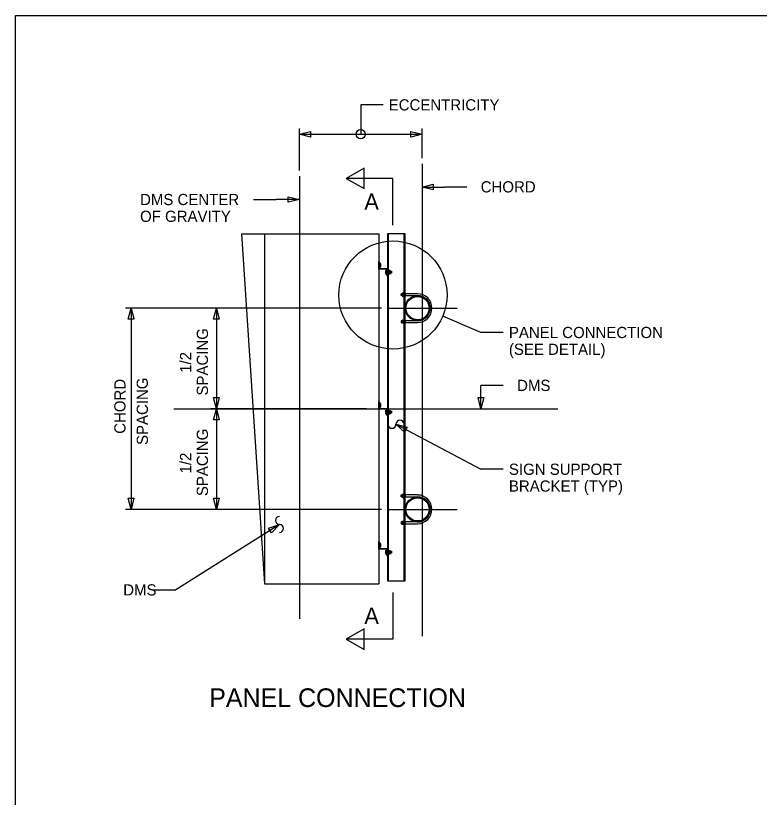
# Model space of a CAD drawing. Extents: x 3831399 to 3833095, y 499014 to 500202.
# Drawn here: x 3832280.2 to 3832479.3, y 499383.6 to 499593 of the extents above; entities that cross this region are included whole.
import ezdxf

# ---------------------------------------------------------------- set-up
doc = ezdxf.new("R2010")
doc.units = 0
for name, color, linetype in [('0-ANCHOR', 7, 'Continuous'), ('2', 7, 'Continuous'), ('CNTR', 7, 'Continuous'), ('Default', 7, 'Continuous'), ('DIM TXT', 7, 'Continuous'), ('sign', 7, 'Continuous'), ('structure', 7, 'Continuous')]:
    doc.layers.add(name, color=color, linetype=linetype)

msp = doc.modelspace()

# ---------------------------------------------------------------- linework, layer by layer
at = {"layer": '0-ANCHOR'}
for p, q in [((3832377.88, 499526.58), (3832377.58, 499526.58)), ((3832377.58, 499526.58), (3832377.58, 499525.75)), ((3832377.88, 499526.37), (3832377.58, 499526.37)), ((3832377.88, 499525.95), (3832377.58, 499525.95)), ((3832377.58, 499525.75), (3832377.88, 499525.75)), ((3832377.92, 499525.79), (3832377.92, 499526.53)), ((3832379.19, 499524.67), (3832379.19, 499523.94)), ((3832379.53, 499524.72), (3832379.24, 499524.72)), ((3832379.53, 499523.89), (3832379.53, 499524.72)), ((3832380.04, 499524.55), (3832379.53, 499524.55)), ((3832380.43, 499524.72), (3832380.04, 499524.72)), ((3832380.04, 499524.72), (3832380.04, 499523.89)), ((3832380.04, 499524.06), (3832380.04, 499524.55)), ((3832380.48, 499523.94), (3832380.48, 499524.67)), ((3832380.48, 499524.55), (3832380.82, 499524.55)), ((3832380.82, 499524.55), (3832380.82, 499524.06)), ((3832379.24, 499524.51), (3832379.53, 499524.51)), ((3832379.24, 499524.1), (3832379.53, 499524.1)), ((3832379.24, 499523.89), (3832379.53, 499523.89)), ((3832379.53, 499524.06), (3832380.04, 499524.06)), ((3832380.04, 499524.51), (3832380.43, 499524.51)), ((3832380.04, 499524.1), (3832380.43, 499524.1)), ((3832380.04, 499523.89), (3832380.43, 499523.89)), ((3832380.82, 499524.06), (3832380.48, 499524.06)), ((3832377.88, 499489.08), (3832377.58, 499489.08)), ((3832377.58, 499489.08), (3832377.58, 499488.25)), ((3832377.92, 499488.29), (3832377.92, 499489.03)), ((3832377.88, 499488.87), (3832377.58, 499488.87)), ((3832377.88, 499488.46), (3832377.58, 499488.46)), ((3832377.58, 499488.25), (3832377.88, 499488.25)), ((3832379.19, 499487.18), (3832379.19, 499486.44)), ((3832379.53, 499487.22), (3832379.24, 499487.22)), ((3832379.24, 499487.02), (3832379.53, 499487.02)), ((3832379.53, 499486.39), (3832379.53, 499487.22)), ((3832380.04, 499487.05), (3832379.53, 499487.05)), ((3832380.43, 499487.22), (3832380.04, 499487.22)), ((3832380.04, 499487.22), (3832380.04, 499486.39)), ((3832380.04, 499486.56), (3832380.04, 499487.05)), ((3832380.04, 499487.02), (3832380.43, 499487.02)), ((3832380.48, 499486.44), (3832380.48, 499487.18)), ((3832380.48, 499487.05), (3832380.82, 499487.05)), ((3832380.82, 499487.05), (3832380.82, 499486.56)), ((3832379.24, 499486.6), (3832379.53, 499486.6)), ((3832379.24, 499486.39), (3832379.53, 499486.39)), ((3832379.53, 499486.56), (3832380.04, 499486.56)), ((3832380.04, 499486.6), (3832380.43, 499486.6)), ((3832380.04, 499486.39), (3832380.43, 499486.39)), ((3832380.82, 499486.56), (3832380.48, 499486.56)), ((3832377.88, 499451.58), (3832377.58, 499451.58)), ((3832377.58, 499451.58), (3832377.58, 499450.75)), ((3832377.88, 499451.37), (3832377.58, 499451.37)), ((3832377.92, 499450.8), (3832377.92, 499451.53)), ((3832377.88, 499450.96), (3832377.58, 499450.96)), ((3832377.58, 499450.75), (3832377.88, 499450.75)), ((3832379.19, 499449.68), (3832379.19, 499448.94)), ((3832379.53, 499449.72), (3832379.24, 499449.72)), ((3832379.24, 499449.52), (3832379.53, 499449.52)), ((3832379.53, 499448.89), (3832379.53, 499449.72)), ((3832380.04, 499449.55), (3832379.53, 499449.55)), ((3832380.43, 499449.72), (3832380.04, 499449.72)), ((3832380.04, 499449.72), (3832380.04, 499448.89)), ((3832380.04, 499449.06), (3832380.04, 499449.55)), ((3832380.04, 499449.52), (3832380.43, 499449.52)), ((3832380.48, 499448.94), (3832380.48, 499449.68)), ((3832380.48, 499449.55), (3832380.82, 499449.55)), ((3832380.82, 499449.55), (3832380.82, 499449.06)), ((3832379.24, 499449.1), (3832379.53, 499449.1)), ((3832379.24, 499448.89), (3832379.53, 499448.89)), ((3832379.53, 499449.06), (3832380.04, 499449.06)), ((3832380.04, 499449.1), (3832380.43, 499449.1)), ((3832380.04, 499448.89), (3832380.43, 499448.89)), ((3832380.82, 499449.06), (3832380.48, 499449.06))]:
    msp.add_line(p, q, dxfattribs=at)
for centre, start, end in [((3832377.88, 499526.53), 360, 90), ((3832377.88, 499526.42), 270, 0), ((3832377.88, 499525.91), 360, 90), ((3832377.88, 499525.79), 270, 0), ((3832379.24, 499524.67), 90, 180), ((3832379.24, 499524.56), 180, 270), ((3832380.43, 499524.67), 360, 90), ((3832380.43, 499524.56), 270, 0), ((3832379.24, 499524.05), 90, 180), ((3832379.24, 499523.94), 180, 270), ((3832380.43, 499524.05), 360, 90), ((3832380.43, 499523.94), 270, 0), ((3832377.88, 499489.03), 360, 90), ((3832377.88, 499488.92), 270, 0), ((3832377.88, 499488.41), 360, 90), ((3832377.88, 499488.29), 270, 0), ((3832379.24, 499487.18), 90, 180), ((3832379.24, 499487.06), 180, 270), ((3832380.43, 499487.18), 360, 90), ((3832380.43, 499487.06), 270, 0), ((3832379.24, 499486.55), 90, 180), ((3832379.24, 499486.44), 180, 270), ((3832380.43, 499486.55), 360, 90), ((3832380.43, 499486.44), 270, 0), ((3832377.88, 499451.53), 360, 90), ((3832377.88, 499451.42), 270, 0), ((3832377.88, 499450.91), 360, 90), ((3832377.88, 499450.8), 270, 0), ((3832379.24, 499449.68), 90, 180), ((3832379.24, 499449.56), 180, 270), ((3832380.43, 499449.68), 360, 90), ((3832380.43, 499449.56), 270, 0), ((3832379.24, 499449.05), 90, 180), ((3832379.24, 499448.94), 180, 270), ((3832380.43, 499449.05), 360, 90), ((3832380.43, 499448.94), 270, 0)]:
    msp.add_arc(centre, 0.0469, start, end, dxfattribs=at)
for centre, major_axis, start_param, end_param in [((3832377.88, 499526.24), (0, 0.129), 4.712389, 6.283185), ((3832377.88, 499526.08), (0, -0.129), 0, 1.570796), ((3832379.24, 499524.38), (0, 0.129), 0, 1.570796), ((3832379.24, 499524.23), (0, -0.129), 4.712389, 6.283185), ((3832380.43, 499524.38), (0, 0.129), 4.712389, 6.283185), ((3832380.43, 499524.23), (0, -0.129), 0, 1.570796), ((3832377.88, 499488.74), (0, 0.129), 4.712389, 6.283185), ((3832377.88, 499488.58), (0, -0.129), 0, 1.570796), ((3832379.24, 499486.89), (0, 0.129), 0, 1.570796), ((3832380.43, 499486.89), (0, 0.129), 4.712389, 6.283185), ((3832379.24, 499486.73), (0, -0.129), 4.712389, 6.283185), ((3832380.43, 499486.73), (0, -0.129), 0, 1.570796), ((3832377.88, 499451.24), (0, 0.129), 4.712389, 6.283185), ((3832377.88, 499451.09), (0, -0.129), 0, 1.570796), ((3832379.24, 499449.39), (0, 0.129), 0, 1.570796), ((3832379.24, 499449.23), (0, -0.129), 4.712389, 6.283185), ((3832380.43, 499449.39), (0, 0.129), 4.712389, 6.283185), ((3832380.43, 499449.23), (0, -0.129), 0, 1.570796)]:
    msp.add_ellipse(centre, major_axis=major_axis, ratio=0.362172, start_param=start_param, end_param=end_param, dxfattribs=at)
at = {"layer": '2'}
for p, q in [((3832280.16, 499029.03), (3832280.16, 499593.03)), ((3832280.16, 499593.03), (3833066.16, 499593.03))]:
    msp.add_line(p, q, dxfattribs=at)
at = {"layer": 'CNTR'}
for p, q in [((3832388.95, 499553.36), (3832388.95, 499426.8)), ((3832356.11, 499550.03), (3832356.11, 499431.49)), ((3832379.58, 499514.69), (3832398.32, 499514.69)), ((3832322.49, 499487.74), (3832425.31, 499487.74)), ((3832379.58, 499460.78), (3832398.32, 499460.78))]:
    msp.add_line(p, q, dxfattribs=at)
at = {"layer": 'Default'}
for p, q in [((3832373.44, 499552.2), (3832368.68, 499549.45)), ((3832373.44, 499546.7), (3832373.44, 499552.2)), ((3832368.68, 499549.45), (3832373.44, 499546.7)), ((3832373.44, 499428.77), (3832368.68, 499426.02)), ((3832373.44, 499423.27), (3832373.44, 499428.77)), ((3832368.68, 499426.02), (3832373.44, 499423.27))]:
    msp.add_line(p, q, dxfattribs=at)
at = {"layer": 'DIM TXT'}
for p, q in [((3832372.53, 499569.13), (3832372.53, 499561.26)), ((3832378.53, 499569.13), (3832372.53, 499569.13)), ((3832356.11, 499551.53), (3832356.11, 499562.76)), ((3832388.95, 499554.86), (3832388.95, 499562.76)), ((3832356.11, 499561.26), (3832388.95, 499561.26)), ((3832381.17, 499549.45), (3832368.68, 499549.45)), ((3832381.17, 499536.95), (3832381.17, 499549.45)), ((3832388.95, 499547.11), (3832394.95, 499547.11)), ((3832400.95, 499547.11), (3832394.95, 499547.11)), ((3832343.86, 499543.78), (3832349.86, 499543.78)), ((3832356.11, 499543.78), (3832349.86, 499543.78)), ((3832378.08, 499514.69), (3832309.57, 499514.69)), ((3832311.07, 499514.69), (3832311.07, 499460.78)), ((3832378.08, 499514.69), (3832332.4, 499514.69)), ((3832333.9, 499514.69), (3832333.9, 499487.74)), ((3832404.71, 499508.16), (3832394.49, 499512.52)), ((3832410.71, 499508.16), (3832404.71, 499508.16)), ((3832404.71, 499487.74), (3832404.71, 499493.99)), ((3832410.71, 499493.99), (3832404.71, 499493.99)), ((3832374.1, 499487.74), (3832332.4, 499487.74)), ((3832374.1, 499487.74), (3832332.4, 499487.74)), ((3832333.9, 499487.74), (3832333.9, 499460.78)), ((3832381.98, 499483.57), (3832404.71, 499471.53)), ((3832410.71, 499471.53), (3832404.71, 499471.53)), ((3832378.08, 499460.78), (3832309.57, 499460.78)), ((3832378.08, 499460.78), (3832332.4, 499460.78)), ((3832350.79, 499456.75), (3832323.01, 499439.22)), ((3832317.01, 499439.22), (3832323.01, 499439.22)), ((3832381.17, 499438.52), (3832381.17, 499426.02)), ((3832381.17, 499426.02), (3832368.68, 499426.02))]:
    msp.add_line(p, q, dxfattribs=at)
for points in [[(3832359.11, 499560.51), (3832356.11, 499561.26), (3832359.11, 499562.01)], [(3832385.95, 499562.01), (3832388.95, 499561.26), (3832385.95, 499560.51)], [(3832391.95, 499546.36), (3832388.95, 499547.11), (3832391.95, 499547.86)], [(3832353.11, 499544.53), (3832356.11, 499543.78), (3832353.11, 499543.03)], [(3832310.32, 499511.69), (3832311.07, 499514.69), (3832311.82, 499511.69)], [(3832333.15, 499511.69), (3832333.9, 499514.69), (3832334.65, 499511.69)], [(3832334.65, 499490.74), (3832333.9, 499487.74), (3832333.15, 499490.74)], [(3832405.46, 499490.74), (3832404.71, 499487.74), (3832403.96, 499490.74)], [(3832333.15, 499484.74), (3832333.9, 499487.74), (3832334.65, 499484.74)], [(3832384.28, 499481.5), (3832381.98, 499483.57), (3832384.98, 499482.83)], [(3832311.82, 499463.78), (3832311.07, 499460.78), (3832310.32, 499463.78)], [(3832334.65, 499463.78), (3832333.9, 499460.78), (3832333.15, 499463.78)], [(3832347.85, 499455.79), (3832350.79, 499456.75), (3832348.65, 499454.52)]]:
    msp.add_lwpolyline(points, close=True, dxfattribs=at)
for centre, radius in [((3832372.53, 499561.26), 1.25), ((3832381.17, 499518.2), 14.48)]:
    msp.add_circle(centre, radius, dxfattribs=at)
for centre, start, end in [((3832380.9, 499483.57), 180, 0), ((3832383.05, 499483.57), 0, 180), ((3832350.79, 499457.83), 90, 270), ((3832350.79, 499455.68), 270, 90)]:
    msp.add_arc(centre, 1.08, start, end, dxfattribs=at)
at = {"layer": 'sign'}
for p, q in [((3832340.58, 499534.61), (3832346.74, 499440.86)), ((3832340.58, 499534.61), (3832377.39, 499534.61)), ((3832346.74, 499534.61), (3832346.74, 499440.86)), ((3832377.39, 499534.61), (3832377.39, 499440.86)), ((3832377.39, 499525.14), (3832377.39, 499527.19)), ((3832377.58, 499526.99), (3832377.58, 499525.53)), ((3832379.34, 499525.14), (3832377.39, 499525.14)), ((3832377.78, 499525.33), (3832379.73, 499525.33)), ((3832379.53, 499523.48), (3832379.53, 499524.94)), ((3832379.73, 499525.33), (3832379.73, 499523.28)), ((3832383.34, 499518.06), (3832383.34, 499518.54)), ((3832383.34, 499518.54), (3832383.67, 499518.54)), ((3832383.67, 499518.66), (3832383.67, 499517.93)), ((3832384.11, 499518.71), (3832383.72, 499518.71)), ((3832384.11, 499518.51), (3832383.72, 499518.51)), ((3832384.11, 499517.62), (3832384.11, 499518.98)), ((3832384.11, 499518.98), (3832384.21, 499518.98)), ((3832384.11, 499517.89), (3832384.11, 499518.71)), ((3832384.21, 499518.98), (3832384.21, 499517.62)), ((3832387.75, 499518.54), (3832384.41, 499518.54)), ((3832384.41, 499518.54), (3832384.41, 499518.06)), ((3832383.67, 499518.06), (3832383.34, 499518.06)), ((3832384.11, 499518.09), (3832383.72, 499518.09)), ((3832383.72, 499517.89), (3832384.11, 499517.89)), ((3832384.21, 499517.62), (3832384.11, 499517.62)), ((3832384.41, 499518.06), (3832387.75, 499518.06)), ((3832383.67, 499511.32), (3832383.34, 499511.32)), ((3832383.34, 499511.32), (3832383.34, 499510.83)), ((3832383.34, 499510.83), (3832383.67, 499510.83)), ((3832383.67, 499510.71), (3832383.67, 499511.44)), ((3832383.72, 499511.49), (3832384.11, 499511.49)), ((3832384.11, 499511.28), (3832383.72, 499511.28)), ((3832384.11, 499510.87), (3832383.72, 499510.87)), ((3832384.11, 499510.66), (3832383.72, 499510.66)), ((3832384.11, 499511.49), (3832384.11, 499510.66)), ((3832387.75, 499511.32), (3832384.41, 499511.32)), ((3832384.41, 499511.32), (3832384.41, 499510.83)), ((3832384.41, 499510.83), (3832387.75, 499510.83)), ((3832377.39, 499487.64), (3832377.39, 499489.69)), ((3832377.58, 499489.49), (3832377.58, 499488.03)), ((3832379.34, 499487.64), (3832377.39, 499487.64)), ((3832377.78, 499487.83), (3832379.73, 499487.83)), ((3832379.53, 499485.98), (3832379.53, 499487.44)), ((3832379.73, 499487.83), (3832379.73, 499485.78)), ((3832383.34, 499464.15), (3832383.34, 499464.64)), ((3832383.34, 499464.64), (3832383.67, 499464.64)), ((3832383.67, 499464.15), (3832383.34, 499464.15)), ((3832383.67, 499464.76), (3832383.67, 499464.03)), ((3832384.11, 499464.81), (3832383.72, 499464.81)), ((3832384.11, 499464.6), (3832383.72, 499464.6)), ((3832384.11, 499464.19), (3832383.72, 499464.19)), ((3832383.72, 499463.98), (3832384.11, 499463.98)), ((3832384.11, 499463.72), (3832384.11, 499465.07)), ((3832384.11, 499465.07), (3832384.21, 499465.07)), ((3832384.11, 499463.98), (3832384.11, 499464.81)), ((3832384.21, 499465.07), (3832384.21, 499463.72)), ((3832387.75, 499464.64), (3832384.41, 499464.64)), ((3832384.41, 499464.64), (3832384.41, 499464.15)), ((3832384.41, 499464.15), (3832387.75, 499464.15)), ((3832384.21, 499463.72), (3832384.11, 499463.72)), ((3832383.67, 499456.81), (3832383.67, 499457.54)), ((3832383.72, 499457.58), (3832384.11, 499457.58)), ((3832384.11, 499457.58), (3832384.11, 499456.76)), ((3832383.67, 499457.41), (3832383.34, 499457.41)), ((3832383.34, 499457.41), (3832383.34, 499456.93)), ((3832383.34, 499456.93), (3832383.67, 499456.93)), ((3832384.11, 499457.38), (3832383.72, 499457.38)), ((3832384.11, 499456.97), (3832383.72, 499456.97)), ((3832384.11, 499456.76), (3832383.72, 499456.76)), ((3832387.75, 499457.41), (3832384.41, 499457.41)), ((3832384.41, 499457.41), (3832384.41, 499456.93)), ((3832384.41, 499456.93), (3832387.75, 499456.93)), ((3832377.39, 499450.14), (3832377.39, 499452.19)), ((3832377.58, 499451.99), (3832377.58, 499450.53)), ((3832379.34, 499450.14), (3832377.39, 499450.14)), ((3832377.78, 499450.33), (3832379.73, 499450.33)), ((3832379.53, 499448.48), (3832379.53, 499449.94)), ((3832379.73, 499450.33), (3832379.73, 499448.28)), ((3832346.74, 499440.86), (3832377.39, 499440.86))]:
    msp.add_line(p, q, dxfattribs=at)
for centre, radius, start, end in [((3832377.39, 499526.99), 0.195, 0, 90), ((3832377.78, 499525.53), 0.195, 180, 270), ((3832379.34, 499524.94), 0.195, 0, 90), ((3832379.73, 499523.48), 0.195, 180, 270), ((3832383.72, 499518.66), 0.0465, 90, 180), ((3832383.72, 499518.55), 0.0465, 180, 270), ((3832387.75, 499514.69), 3.85, 270, 90), ((3832383.72, 499518.05), 0.0465, 90, 180), ((3832383.72, 499517.93), 0.0465, 180, 270), ((3832387.75, 499514.69), 3.37, 270, 90), ((3832383.72, 499511.44), 0.0465, 90, 180), ((3832383.72, 499511.33), 0.0465, 180, 270), ((3832383.72, 499510.82), 0.0465, 90, 180), ((3832383.72, 499510.71), 0.0465, 180, 270), ((3832377.39, 499489.49), 0.195, 0, 90), ((3832377.78, 499488.03), 0.195, 180, 270), ((3832379.34, 499487.44), 0.195, 0, 90), ((3832379.73, 499485.98), 0.195, 180, 270), ((3832383.72, 499464.76), 0.0465, 90, 180), ((3832383.72, 499464.65), 0.0465, 180, 270), ((3832383.72, 499464.14), 0.0465, 90, 180), ((3832383.72, 499464.03), 0.0465, 180, 270), ((3832387.75, 499460.78), 3.85, 270, 90), ((3832387.75, 499460.78), 3.37, 270, 90), ((3832383.72, 499457.54), 0.0465, 90, 180), ((3832383.72, 499457.42), 0.0465, 180, 270), ((3832383.72, 499456.92), 0.0465, 90, 180), ((3832383.72, 499456.81), 0.0465, 180, 270), ((3832377.39, 499451.99), 0.195, 0, 90), ((3832377.78, 499450.53), 0.195, 180, 270), ((3832379.34, 499449.94), 0.195, 0, 90), ((3832379.73, 499448.48), 0.195, 180, 270)]:
    msp.add_arc(centre, radius, start, end, dxfattribs=at)
for centre, major_axis, start_param, end_param in [((3832383.72, 499518.38), (0, 0.128), 0, 1.570796), ((3832383.72, 499518.22), (0, -0.128), 4.712389, 6.283185), ((3832383.72, 499511.15), (0, 0.128), 0, 1.570796), ((3832383.72, 499511), (0, -0.128), 4.712389, 6.283185), ((3832383.72, 499464.47), (0, 0.128), 0, 1.570796), ((3832383.72, 499464.32), (0, -0.128), 4.712389, 6.283185), ((3832383.72, 499457.25), (0, 0.128), 0, 1.570796), ((3832383.72, 499457.09), (0, -0.128), 4.712389, 6.283185)]:
    msp.add_ellipse(centre, major_axis=major_axis, ratio=0.362172, start_param=start_param, end_param=end_param, dxfattribs=at)
at = {"layer": 'structure'}
for p, q in [((3832384.41, 499534.61), (3832379.73, 499534.61)), ((3832379.73, 499534.61), (3832379.73, 499441.64)), ((3832384.21, 499534.61), (3832379.93, 499534.61)), ((3832379.93, 499534.61), (3832379.93, 499441.64)), ((3832384.21, 499441.64), (3832384.21, 499534.61)), ((3832384.41, 499441.64), (3832384.41, 499534.61)), ((3832379.73, 499441.64), (3832384.41, 499441.64)), ((3832379.93, 499441.64), (3832384.21, 499441.64))]:
    msp.add_line(p, q, dxfattribs=at)
for centre, radius in [((3832387.75, 499514.69), 3.34), ((3832387.75, 499514.69), 3.1), ((3832387.75, 499460.78), 3.34), ((3832387.75, 499460.78), 3.1)]:
    msp.add_circle(centre, radius, dxfattribs=at)

# ---------------------------------------------------------------- texts
at = {"layer": 'Default'}
msp.add_text('PANEL CONNECTION', height=4.9999, dxfattribs=at).set_placement((3832331.98, 499407.84))
at = {"layer": 'DIM TXT'}
for s, height, p in [('ECCENTRICITY', 2.9999, (3832380.03, 499567.63)), ('  CHORD', 3, (3832402.43, 499545.67)), ('DMS CENTER', 3, (3832313.47, 499542.28)), ('A', 4.37, (3832373.5, 499541.02)), ('OF GRAVITY', 3, (3832313.47, 499537.78)), ('PANEL CONNECTION', 2.9999, (3832412.21, 499506.66)), ('(SEE DETAIL)', 2.9999, (3832412.21, 499502.16)), ('  DMS', 3, (3832412.18, 499492.49)), ('SIGN SUPPORT ', 2.9999, (3832412.21, 499470.03)), ('BRACKET (TYP)', 2.9999, (3832412.21, 499465.53)), ('DMS', 3, (3832308.96, 499437.72)), ('A', 4.37, (3832373.5, 499430.08))]:
    msp.add_text(s, height=height, dxfattribs=at).set_placement(p)
for s, p in [('SPACING', (3832331.65, 499491.28)), ('1/2', (3832327.15, 499497.36)), ('CHORD', (3832309.57, 499481.03)), ('SPACING', (3832315.57, 499478.03)), ('SPACING', (3832331.65, 499464.33)), ('1/2', (3832327.15, 499470.41))]:
    msp.add_text(s, height=3, rotation=90, dxfattribs=at).set_placement(p)

doc.saveas('drawing.dxf')
